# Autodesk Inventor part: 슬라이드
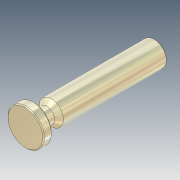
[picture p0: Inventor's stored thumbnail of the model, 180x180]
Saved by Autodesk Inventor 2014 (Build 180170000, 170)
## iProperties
Company: 한국ATC센터
Created: 2014-10
Part Number: 슬라이드
Document SubType Name: Modeling
Designer: 한국ATC센터
Density: 7.86 g/cm^3
Material: 강, 연강
Mass: 735.303 g
Surface Area: 161.098 cm^2
Volume: 93.55 cm^3
Appearance: 티타늄 - 광택
Author: KYOUNG IL JANG
Revision Number: 1
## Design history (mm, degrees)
sketch "스케치1"
  geometry: L1 (-14, 195)-(-14, 171) reference; L2 (19, 106.5)-(-19, 106.5) reference; L3 (0, 106.5)-(0, 256.5); L4 (0, 256.5)-(-14, 256.5); L5 (-14, 256.5)-(-14, 136.5); L6 (-14, 116.5)-(-21, 116.5); L7 (-21, 116.5)-(-21, 106.5); L8 (-21, 106.5)-(0, 106.5); L9 (-14, 116.5)-(-9, 116.5); L10 (-9, 116.5)-(-9, 131.5); L11 (-9, 131.5)-(-14, 136.5); L12 (-14, 136.5)-(-14, 116.5); 1 further point
  constraints: 24 end point, 5 perpendicular, 3 parallel, 1 collinear, 1 horizontal, 1 midpoint, 1 point on line, 1 vertical, 4 other
  dimensions: "d0" = 10 distance between parallel lines of L6 L8; "d1" = 42 diameter of L7 L3; "d2" = 150 distance of L3.start L3.end; "d3" = 135 deg angle of L11 L5; "d4" = 18 diameter of L10 L3; "d5" = 30 distance from line of L5.end L8
revolve "회전1" sketch "스케치1" stored, may be unused: angle "d6" = 90 deg
chamfer "모따기1" distance "d7" = 1; stored, may be unused: second distance "d8" = 2, angle "d9" = 45 deg
fillet "모깎기1" dims "d10" = 2
node "솔리드1"
